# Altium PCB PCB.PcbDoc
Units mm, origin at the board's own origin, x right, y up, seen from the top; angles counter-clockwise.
Board outline 37 x 42.5 mm, 2 copper layers (Top Layer, Bottom Layer); 37 components, 35 nets, 169 pads, 249 vias.
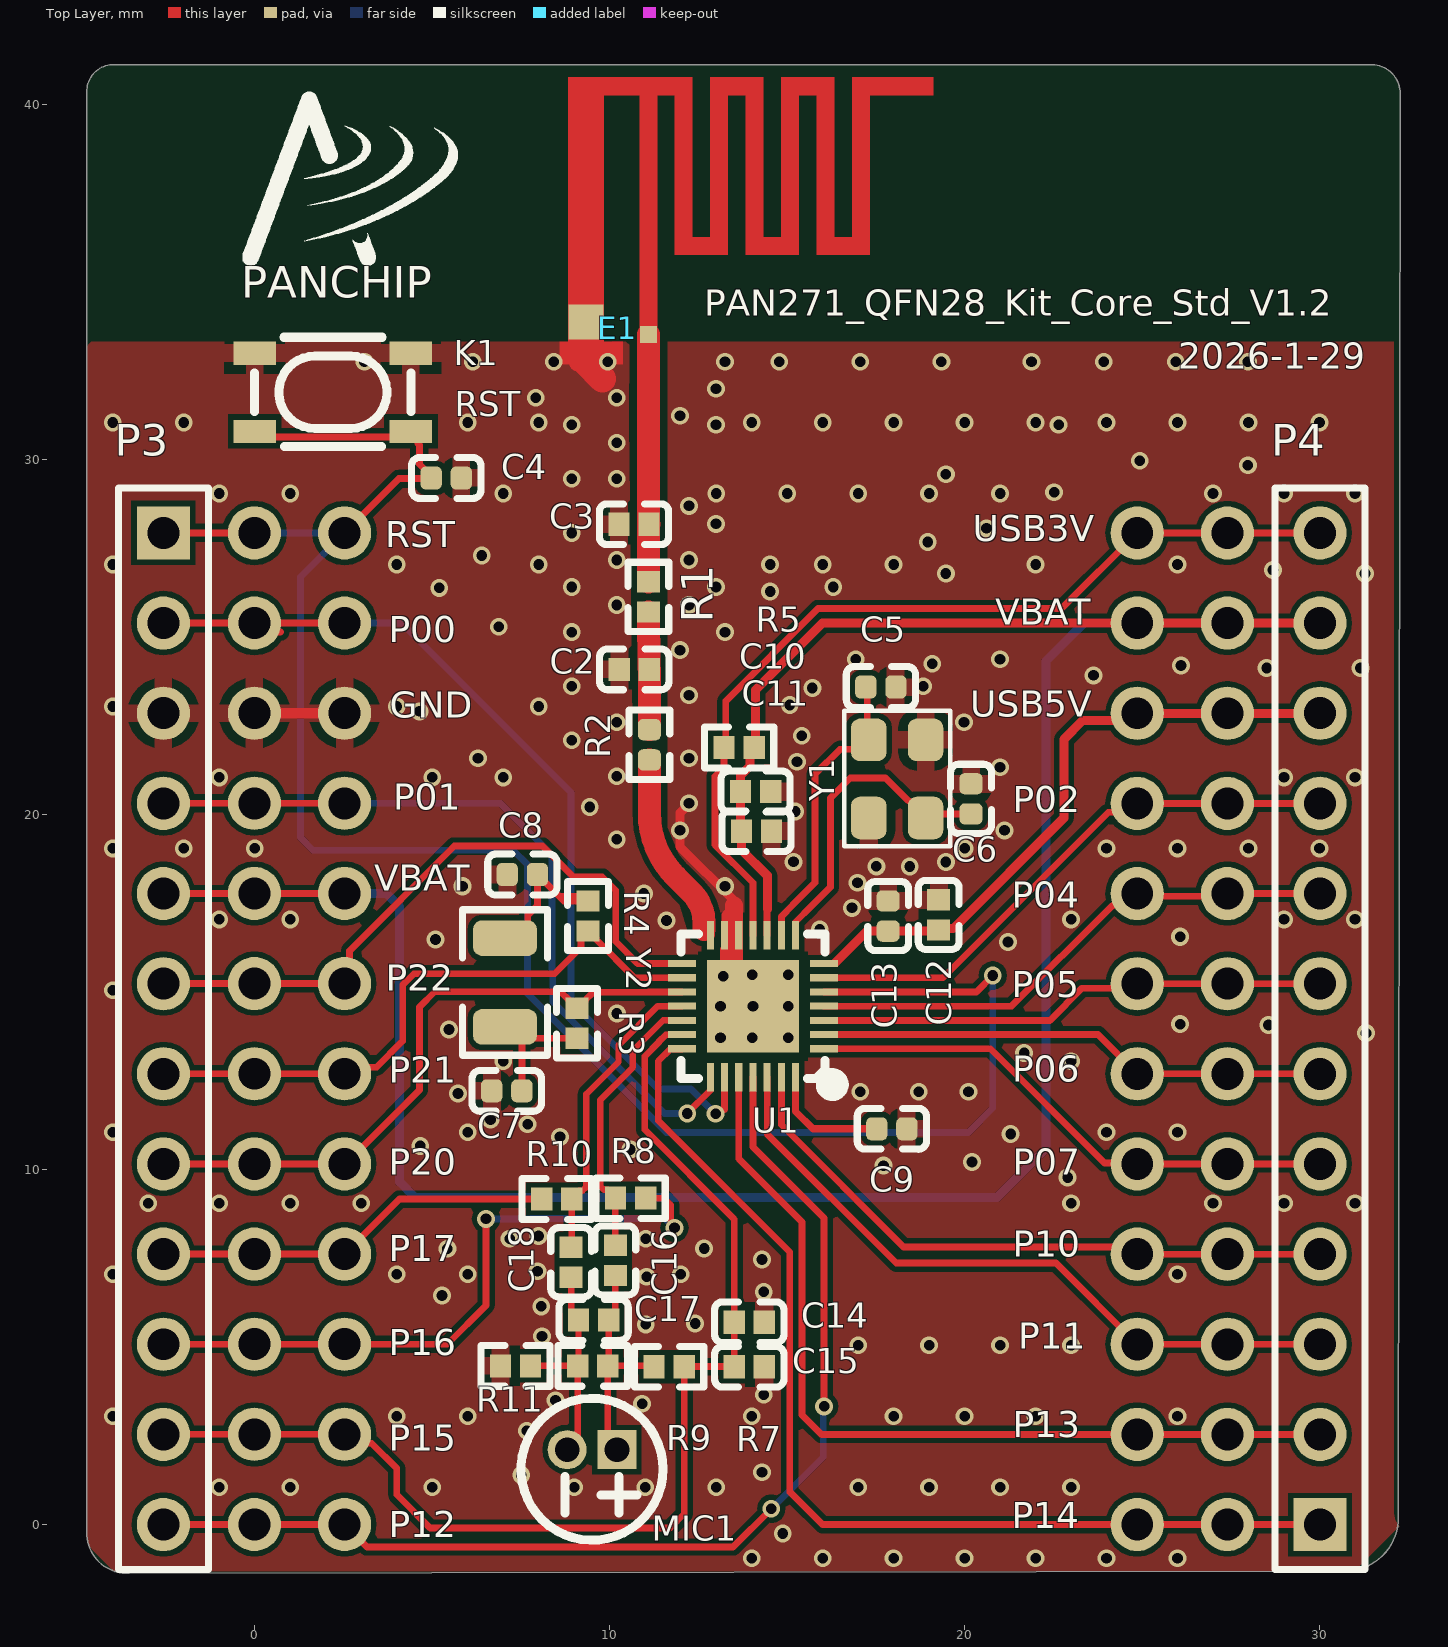
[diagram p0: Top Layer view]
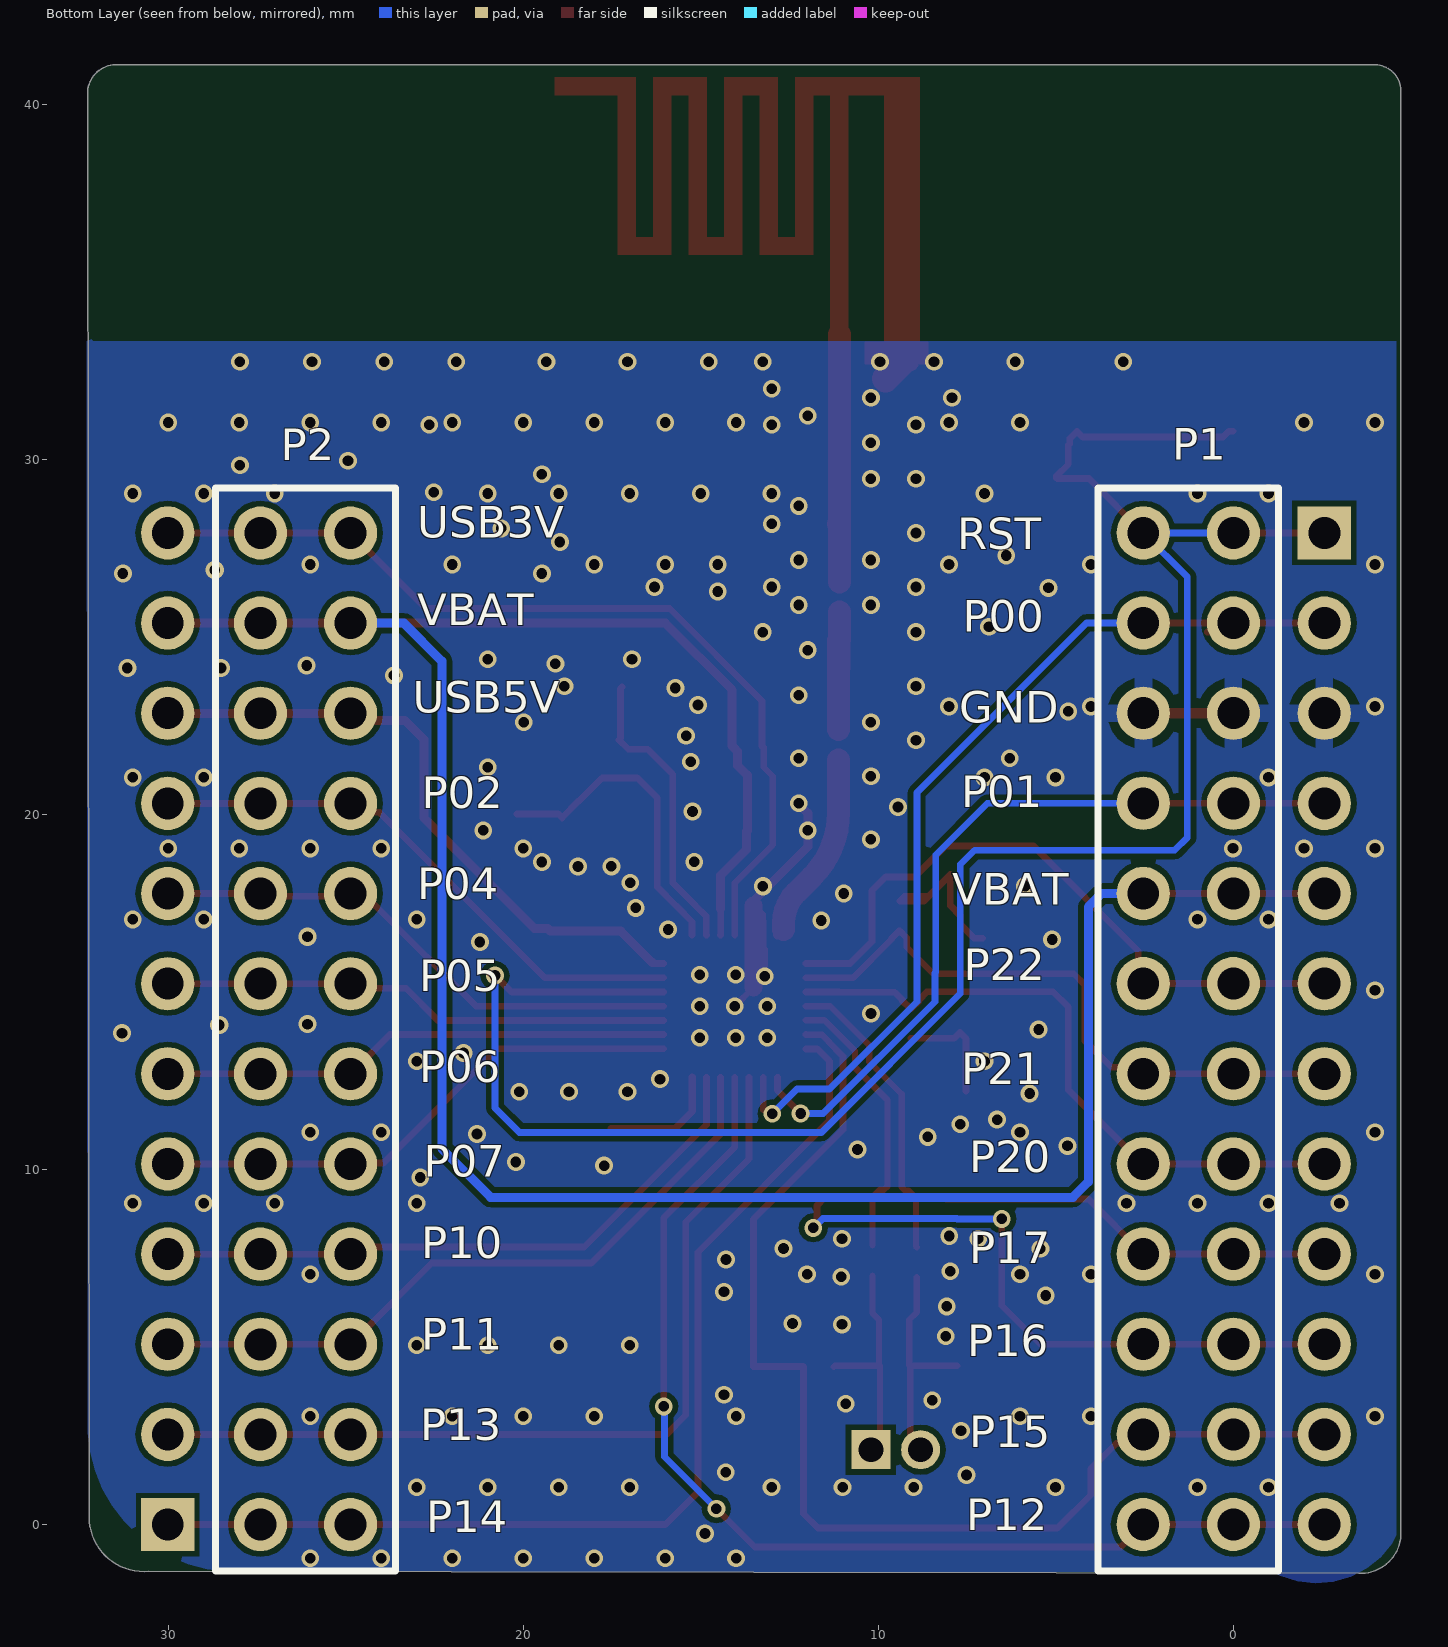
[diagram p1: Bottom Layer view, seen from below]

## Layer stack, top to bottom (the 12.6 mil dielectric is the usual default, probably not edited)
Top Solder: solder mask 0.0102, Solder Resist, Dk 3.5
Top Layer: signal copper 0.0356
Dielectric1: dielectric 0.32, FR-4, Dk 4.8
Bottom Layer: signal copper 0.0356
Bottom Solder: solder mask 0.0102, Solder Resist, Dk 3.5

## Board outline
-4.719,-0.306 -4.719,40.359 cw(c-3.98,40.39) -4.011,41.129 31.499,41.129 cw(c31.482,40.325) 32.285,40.309 32.235,0.075 cw(c30.699,0.215) 30.559,-1.322 30.559,-1.323 -3.528,-1.373 cw(c-3.59,-0.244)

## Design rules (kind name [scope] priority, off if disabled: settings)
Clearance Clearance_SMT [OnLayer('Keep-Out Layer')] p1: gap=0.127
Clearance Clearance_ANT [InNetClass('ANT_Class')] p2: gap=0.117
Clearance [All] p3: gap=0.152
ComponentClearance [All] p1 off: gap=0.254 collisioncheckmode=3 verticalgap=0.254 showdistances=FALSE
DiffPairsRouting [All] p1: maxlimit=0.254 minlimit=0.178 mostfreqgap=0.254 toplayer_minwidth=0.178 toplayer_maxwidth=0.381 toplayer_prefwidth=0.178 bottomlayer_minwidth=0.178 bottomlayer_maxwidth=0.381 bottomlayer_prefwidth=0.178 maxuncoupledlength=12.7
HoleSize [All] p1: absolutevalues=TRUE maxlimit=2.54 minlimit=0.254 maxpercent=80.000 minpercent=20.000
HoleToHoleClearance [All] p1: gap=0.2 allowstackedmicrovias=TRUE
MinimumSolderMaskSliver MinimumSolderMaskSliver_1 [HasFootprint('QFN-28_5x5x05P')] p1: minsoldermaskwidth=0.017
MinimumSolderMaskSliver [All] p2: minsoldermaskwidth=0.02
NetAntennae [All] p1 off: netantennaetolerance=0
PlaneConnect [All] p1: planeconnectstyle=Relief reliefexpansion=0.508 reliefentries=4 reliefconductorwidth=0.508 reliefairgap=0.254
PolygonConnect PolygonConnect_VIA [IsVia] p1: connectstyle=Direct reliefconductorwidth=0.254 reliefentries=4 polygonreliefangle="90 Angle" airgapwidth=0.254
PolygonConnect [All] p2: connectstyle=Relief reliefconductorwidth=0.508 reliefentries=4 polygonreliefangle="90 Angle" airgapwidth=0.254
RoomDefinition ANT [False] p1: confinementstyle=ConfineIn formatcopy=TRUE lockcomponents=FALSE outline 7.061,40.999 25.248,40.999 25.248,32.099 7.061,32.099
RoutingVias [All] p1: holewidth=0.4 width=0.5 viastyle="Through Hole" minholewidth=0.3 minwidth=0.5 maxholewidth=0.5 maxwidth=0.7
ShortCircuit ShortCircuit_ANT [WithinRoom('ANT')] p1: allowed=TRUE
ShortCircuit [All] p2: allowed=FALSE
SilkToSilkClearance [All] p1: silktosilkclearance=0
SilkToSolderMaskClearance SilkToSolderMaskClearance_U10 [HasFootprint('U2')] p1: minsilkscreentomaskgap=0.051 clearancetoexposedcopper=TRUE
SilkToSolderMaskClearance [IsPad] p2: minsilkscreentomaskgap=0 clearancetoexposedcopper=TRUE
SolderMaskExpansion SolderMaskExpansion_1 [IsVia] p1: expansion=0.102
Width [All] p1: maxlimit=1.27 minlimit=0.191 preferedwidth=0.191
20 further rules are at their usual default settings.

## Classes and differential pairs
differential pair mic1: +mic1_p -mic1_n
differential pair mic: +mic_p -mic_n

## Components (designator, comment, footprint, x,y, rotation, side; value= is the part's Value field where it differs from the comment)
C2 "NC" 0402_C#1 10.703,24.094 r180 top
C3 "NC" 0402_C#1 10.696,28.183 r180 top
C4 "100nF / NC" 0402_C#2 5.406,29.488 r180 top
C5 "NC" 0402_C#2 17.653,23.597 r0 top
C6 "NC" 0402_C#2 20.193,20.447 r90 top
C7 "18pF" 0402_C#2 7.112,12.217 r180 top
C8 "18pF" 0402_C#2 7.551,18.313 r180 top
C9 "NC" 0402_C#2 17.96,11.149 r180 top
C10 "4.7uF" 0402_C#1 14.122,20.65 r180 top
C11 "100nF" 0402_C#1 14.148,19.533 r180 top
C12 "100nF" 0402_C#1 19.281,17.176 r270 top
C13 "4.7uF" 0402_C#2 17.859,17.144 r270 top
C14 "NC/4.7uF" 0402_C#1 13.943,5.699 r180 top
C15 "NC/100nF" 0402_C#1 13.945,4.445 r180 top
C16 "NC/1uF" 0402_C#1 10.169,7.441 r270 top
C17 "NC" 0402_C#1 9.56,5.765 r180 top
C18 "NC/1uF" 0402_C#1 8.925,7.39 r270 top
E1 "ANT_PCB" 2.4G_PF_SUB1.5mm_ADD1 9.347,33.579 r90 top
K1 "K2-1808GN-A4SW-04" KEY-SMD_4P-L4.2-W3.2-P2.20-LS5.1-TL 2.21,31.902 r180 top
MIC1 "GMI4015P-2C-60db" MIC-TH_BD4.0-P1.40-D0.4-L-FD 9.513,2.107 r180 top
P1 "Header 2x12" "Header 2X12" 2.54,27.94 r270 bottom locked
P2 "Header 2x12" "Header 2X12" 27.415,27.938 r270 bottom locked
P3 "nc" HDR1X12 -2.563,27.939 r270 top
P4 "nc" HDR1X12 30.025,-0.001 r90 top
R1 "0Ω" 0402_R#1 11.1,26.137 r90 top
R2 "0Ω" 0402_R#2 11.128,21.97 r90 top
R3 "NC" 0402_R#1 9.093,14.122 r270 top
R4 "NC" 0402_R#1 9.398,17.145 r90 top
R5 "NC" 0402_R#1 13.658,21.895 r180 top
R7 "2.2KΩ" 0402_R#1 11.687,4.444 r0 top
R8 "0Ω" 0402_R#1 10.601,9.194 r180 top
R9 "NC" 0402_R#1 9.534,4.469 r0 top
R10 "0Ω" 0402_R#1 8.518,9.168 r0 top
R11 "2.2KΩ" 0402_R#1 7.357,4.469 r0 top
U1 "pn271_qfn28" QFN28_L4.0_W4.0_P0.40_BL_EP 14.049,14.604 r90 top
Y1 "32MHz 10pF ±10ppm" SMD-3225_4P_S 18.11,21.006 r90 top
Y2 "32.768KHz" "SMD-3215_2P FC - 135" 7.061,15.271 r90 top

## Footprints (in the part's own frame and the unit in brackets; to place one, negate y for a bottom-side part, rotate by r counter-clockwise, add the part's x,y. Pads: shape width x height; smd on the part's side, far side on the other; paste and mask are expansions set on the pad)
2.4G_PF_SUB1.5mm_ADD1 [mil] "FR4_PCB with 1.6mm thickness"
  rect 19x19 smd: 1(-2,-69)
  rect 39x39 smd: 2(12,0)
  Top Layer region: 283.31,-19.48 283.31,19.89 -12,19.89 -12,-19.48
  Top Layer region: 283.31,-314.76 263.61,-314.76 263.61,-385 283.31,-385
  Top Layer region: 283.31,-236.02 283.31,-216.33 86.46,-216.33 86.46,-236.02 283.31,-236.02
  Top Layer region: 283.31,-314.76 283.31,-295.07 86.46,-295.07 86.46,-314.76 283.31,-314.76
  Top Layer region: 283.31,-196.64 283.31,-176.96 86.46,-176.96 86.46,-196.64 283.31,-196.64
  Top Layer region: 283.31,-275.39 283.31,-255.7 86.46,-255.7 86.46,-275.39 283.31,-275.39
  Top Layer region: 283.31,-157.28 283.31,-137.59 86.46,-137.59 86.46,-157.28 283.31,-157.28
  Top Layer region: 283.31,-255.7 283.31,-236.02 263.62,-236.02 263.62,-255.7 283.31,-255.7
  Top Layer region: 283.31,-117.91 283.31,-19.48 263.62,-19.48 263.62,-98.22 86.46,-98.22 86.46,-117.91 283.31,-117.91
  Top Layer region: 283.31,-176.96 283.31,-157.28 263.62,-157.28 263.62,-176.96 283.31,-176.96
  Top Layer region: 106.14,-137.59 106.14,-117.91 86.46,-117.91 86.46,-137.59 106.14,-137.59
  Top Layer region: 106.14,-275.39 86.46,-275.39 86.46,-295.07 106.14,-295.07 106.14,-275.39
  Top Layer region: 106.14,-216.33 106.14,-196.65 86.46,-196.65 86.46,-216.33 106.14,-216.33
  Top Layer region: 263.79,-79.16 263.79,-59.48 -12,-59.48 -12,-79.16
0402_C#1 [mm]
  rect 0.6x0.65 smd mask+0.051: 1(-0.425,0) 2(0.425,0)
  silkscreen extent -0.97,-0.58 0.97,0.58, body extent -0.48,-0.3 0.52,0.3, height 0.2
0402_C#2 [mm]
  rrect50% 0.6x0.65 smd mask+0.051: 1(-0.425,0) 2(0.425,0)
  silkscreen extent -0.97,-0.58 0.98,0.58, body extent -0.48,-0.3 0.52,0.3, height 0.2
0402_R#1 [mm]
  rect 0.6x0.65 smd mask+0.051: 1(-0.425,0) 2(0.425,0)
  silkscreen extent -0.97,-0.58 0.97,0.58, body extent -0.57,-0.27 0.58,0.28, height 0.41
0402_R#2 [mm]
  rrect50% 0.6x0.65 smd mask+0.051: 1(-0.425,0) 2(0.425,0)
  silkscreen extent -0.97,-0.58 0.97,0.58, body extent -0.57,-0.27 0.58,0.28, height 0.41
HDR1X12 [mm] "Connector; Header; 12 Position"
  rect 1.5x1.5 hole 0.9: 1(0,0)
  round 1.5 hole 0.9: 2(2.54,0) 3(5.08,0) 4(7.62,0) 5(10.16,0) 6(12.7,0) 7(15.24,0) 8(17.78,0) 9(20.32,0) 10(22.86,0) 11(25.4,0) 12(27.94,0)
  silkscreen extent -1.27,-1.27 29.21,1.27
"Header 2X12" [mm] "Connector; Header; 12x2 Position"
  round 1.5 hole 0.9: 1(0,0) 2(0,2.54) 3(2.54,0) 4(2.54,2.54) 5(5.08,0) 6(5.08,2.54) 7(7.62,0) 8(7.62,2.54) 9(10.16,0) 10(10.16,2.54) 11(12.7,0) 12(12.7,2.54) 13(15.24,0) 14(15.24,2.54) 15(17.78,0) 16(17.78,2.54) 17(20.32,0) 18(20.32,2.54) 19(22.86,0) 20(22.86,2.54) 21(25.4,0) 22(25.4,2.54) 23(27.94,0) 24(27.94,2.54)
  silkscreen extent -1.27,-1.27 29.25,3.81, body extent -1.27,-1.27 29.21,3.81, height 8.5
KEY-SMD_4P-L4.2-W3.2-P2.20-LS5.1-TL [mm]
  rect 1.2x0.65 smd: 1(-2.2,1.1) 2(2.2,1.1) 3(-2.2,-1.1) 4(2.2,-1.1)
  silkscreen extent -2.2,-1.55 2.2,1.52, body extent -2.55,-1.6 2.65,1.65, height 2.5
MIC-TH_BD4.0-P1.40-D0.4-L-FD [mm]
  rect 1.1x1.1 hole 0.7: 1(-0.7,0)
  round 1.1 hole 0.7: 2(0.7,0)
  silkscreen extent -2,-1.45 2,2.55
QFN28_L4.0_W4.0_P0.40_BL_EP [mm] "271_qfn28_sram"
  rect 0.2x0.8 smd: 1(-1.2,-2) 2(-0.8,-2) 3(-0.4,-2) 4(0,-2) 5(0.4,-2) 6(0.8,-2) 7(1.2,-2) 15(1.2,2) 16(0.8,2) 17(0.4,2) 18(0,2) 19(-0.4,2) 20(-0.8,2) 21(-1.2,2)
  rect 0.8x0.2 smd: 8(2,-1.2) 9(2,-0.8) 10(2,-0.4) 11(2,0) 12(2,0.4) 13(2,0.8) 14(2,1.2) 22(-2,1.2) 23(-2,0.8) 24(-2,0.4) 25(-2,0) 26(-2,-0.4) 27(-2,-0.8) 28(-2,-1.2)
  rect 2.6x2.6 smd: 29(0,0)
  silkscreen extent -2.03,-2.03 2.03,2.03, body extent -1.94,-2.04 2.06,1.96, height 0.75
"SMD-3215_2P FC - 135" [mm]
  rrect50% 1x1.8 smd: 1(-1.25,0) 2(1.25,0)
  silkscreen extent -2.05,-1.2 2.05,1.2, body extent -1.6,-0.75 1.6,0.75, height 0.9
SMD-3225_4P_S [mm]
  rrect50% 1.2x1 smd: 1(1.1,0.8) 2(-1.1,0.8) 3(-1.1,-0.8) 4(1.1,-0.8)
  silkscreen extent -1.9,-1.5 1.92,1.5, body extent -1.6,-1.25 1.6,1.25, height 0.7

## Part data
C2 C3: library part "0402 1nF (102) 10% 50V", "贴片电容"
C4 C9 C13: library part "0402 100nF (104) 10% 16V", "贴片电容"
C5 C6 C7 C8: library part "0402 20pF (200) 5% 50V", "贴片电容"
C10 C11 C12 C14 C15 C16 C17 C18: library part "0402 4.7uF (475) 20% 10V", "贴片电容"
E1: "NC"
P1 P2: "Header 2x11,2.54mm"
P3 P4: library part "Header 12", "Header, 12-Pin"
R1 R2 R3 R4 R5 R9 R11: library part "0402 0Ω (0R0) 1%", "贴片电阻"
R7: library part "0402 2.2KΩ (2201) 1%", "贴片电阻"
R8 R10: library part "0402 0Ω (0R0) 1%"
Y1: library part "Crystal 4pin", "C113671"
Y2: library part "DT26N 32.768KHz", "C620155, X321532768KGD2SI,12.5pF"

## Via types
v1: diameter 0.5, hole 0.3, Top Layer to Bottom Layer, tented both sides, 222 vias
v2: diameter 0.508, hole 0.305, Top Layer to Bottom Layer, tented both sides, 27 vias

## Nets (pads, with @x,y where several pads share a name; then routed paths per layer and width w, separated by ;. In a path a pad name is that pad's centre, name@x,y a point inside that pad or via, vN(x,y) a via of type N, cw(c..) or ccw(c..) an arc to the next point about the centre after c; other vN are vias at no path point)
ANT: R2.1 U1.14 | length 5.9
  Top Layer w0.254: 12.714,17.251 cw(c12.389,16.926) 12.849,16.926 U1.14
  Top Layer w0.65: R2.1 11.128,20.05 ccw(c13.668,20.05) 11.872,18.254 12.322,17.804 cw(c11.477,16.96) 12.671,16.96 12.671,16.765
GND: C2.2 C3.2 C4.1 C5.2 C6.2 C7.2 C8.2 C9.1 C10.1 C11.1 C12.1 C13.1 C14.1 C15.1 E1.2 K1.3 K1.4 P1.5 P1.6 P3.3 R11.1 U1.12 U1.13 U1.29 Y1.2 Y1.4 | length 14.8
  Top Layer w0.191: 13.515,17.441 13.262,17.188 13.262,17.024 13.253,17.016 13.253,16.609 U1.13 13.244,16.599 13.244,16.234 13.208,16.198 13.208,16.078 v1(13.208,15.444) 13.515,15.137 v1(14.049,14.604)
  Top Layer w0.254: v1(12.245,20.319) 12.245,20.301 11.991,20.047 v1(11.991,19.557) 11.991,19.098 13.515,17.574 13.515,17.441
  Top Layer w0.3: P1.6 P1.5
  Top Layer w0.508: 9.119,32.741 9.302,32.924 9.302,33.838 E1.2 ; U1.29@13.515,15.137 13.515,17.441
  Top Layer w0.762: E1.2 9.347,32.741 9.804,32.283
  other v1: 14.011,-0.95 16.011,-0.95 18.011,-0.95 20.011,-0.95 22.011,-0.95 24.011,-0.95 26.011,-0.95 14.887,-0.255 -0.989,1.05 1.011,1.05 5.011,1.05 9.011,1.05 11.011,1.05 13.011,1.05 17.011,1.05 19.011,1.05 21.011,1.05 23.011,1.05 7.521,1.396 14.303,1.472 7.673,2.64 -3.989,3.05 4.011,3.05 6.011,3.05 14.011,3.05 18.011,3.05 20.011,3.05 22.011,3.05 26.011,3.05 10.925,3.402 8.486,3.504 14.351,3.658 17.011,5.05 19.011,5.05 21.011,5.05 23.011,5.05 8.105,5.307 11.026,5.638 8.08,6.146 5.286,6.45 14.351,6.553 11.052,6.984 -3.989,7.05 4.011,7.05 6.011,7.05 12.011,7.05 26.011,7.05 7.978,7.136 5.438,7.771 7.191,8.051 11.026,8.051 8.004,8.127 -2.989,9.05 -0.989,9.05 1.011,9.05 3.011,9.05 23.011,9.05 27.011,9.05 29.011,9.05 31.011,9.05 22.913,9.778 4.676,10.667 8.613,10.921 -3.989,11.05 6.011,11.05 24.011,11.05 26.011,11.05 7.699,11.276 17.071,12.191 18.722,12.191 20.119,12.191 7.011,13.05 23.011,13.05 13.134,13.715 14.023,13.715 15.039,13.715 13.134,14.604 15.039,14.604 -3.989,15.05 14.023,15.493 15.039,15.493 15.928,16.763 11.61,17.017 -0.989,17.05 1.011,17.05 23.011,17.05 29.011,17.05 31.011,17.05 16.84,17.374 10.975,17.779 16.993,18.085 17.526,18.542 18.468,18.541 15.189,18.669 19.484,18.668 -3.989,19.05 -1.989,19.05 0.011,19.05 20.011,19.05 24.011,19.05 26.011,19.05 28.011,19.05 30.011,19.05 10.213,19.303 21.135,19.557 15.24,20.091 9.451,20.217 -0.989,21.05 5.011,21.05 7.011,21.05 29.011,21.05 31.011,21.05 10.213,21.081 21.008,21.335 15.291,21.488 6.302,21.589 12.245,21.589 8.943,22.097 15.42,22.224 10.213,22.605 19.992,22.605 4.651,22.91 -3.989,23.05 4.011,23.05 8.011,23.05 15.088,23.089 12.245,23.367 15.723,23.571 8.943,23.621 18.849,23.621 19.103,24.256 16.944,24.383 21.008,24.383 11.991,24.637 8.943,25.145 13.261,25.145 6.886,25.297 10.213,25.907 12.245,25.907 14.531,26.288 5.21,26.389 8.943,26.415 13.007,26.415 16.309,26.415 19.484,26.796 -3.989,27.05 4.011,27.05 8.011,27.05 14.531,27.05 16.011,27.05 18.011,27.05 22.011,27.05 26.011,27.05 10.213,27.177 12.245,27.177 6.403,27.304 18.976,27.685 8.943,27.939 20.627,28.066 13.007,28.193 12.245,28.701 -0.989,29.05 1.011,29.05 7.011,29.05 13.011,29.05 15.011,29.05 17.011,29.05 19.011,29.05 21.011,29.05 27.011,29.05 29.011,29.05 31.011,29.05 22.532,29.082 8.943,29.463 10.213,29.463 19.484,29.59 27.993,29.844 24.945,29.971 10.213,30.479 8.943,30.987 13.007,30.987 22.659,30.987 -3.989,31.05 -1.989,31.05 6.011,31.05 8.011,31.05 14.011,31.05 16.011,31.05 18.011,31.05 20.011,31.05 22.011,31.05 24.011,31.05 26.011,31.05 28.011,31.05 30.011,31.05 11.991,31.241 7.927,31.749 10.213,31.749 13.007,32.003 3.101,32.765 6.149,32.765 8.435,32.765 9.959,32.765 13.261,32.765 14.785,32.765 17.071,32.765 19.357,32.765 21.897,32.765 23.929,32.765 25.961,32.765 27.993,32.765
  other v2: 12.421,5.664 14.3,7.468 12.675,7.772 17.729,10.109 20.218,10.211 10.592,10.566 21.311,10.998 6.655,11.405 5.74,12.141 16.154,12.548 21.692,13.284 31.318,13.843 5.486,13.945 28.575,14.072 26.086,14.097 10.211,14.402 21.234,16.408 5.105,16.485 26.086,16.561 5.867,17.983 13.259,17.983 23.647,23.927 28.524,24.13 31.166,24.13 26.111,24.206 31.293,26.797 28.702,26.899
mic1_n: C18.1 R10.2 U1.18 | length 8.5
  Top Layer w0.178: C18.1 8.943,7.834 8.943,9.193 9.155,9.404 9.243,9.404 9.347,9.508 9.347,12.128 10.262,13.042 10.262,13.508 11.357,14.604 U1.18
mic1_p: C16.1 R8.2 U1.19 | length 7.8
  Top Layer w0.178: C16.1 10.169,9.187 R8.2 10.176,9.219 9.965,9.43 9.851,9.43 9.747,9.534 9.747,11.962 10.662,12.877 10.662,13.343 11.523,14.204 U1.19
mic_n: C17.2 C18.2 MIC1.2 R9.1 R11.2 | length 6.4
  Top Layer w0.178: R11.2 R9.1 ; MIC1.2 8.813,2.139 9.109,2.435 R9.1 ; C18.2 8.925,5.975 C17.2 9.135,4.495 R9.1
mic_p: C16.2 C17.1 MIC1.1 R7.1 R9.2 | length 6.4
  Top Layer w0.178: C16.2 10.169,5.949 C17.1 9.985,4.495 R9.2 ; MIC1.1 10.159,2.161 10.159,2.226 9.959,2.426 R9.2 ; R7.1 11.236,4.469 R9.2
NetC2_1: C2.1 R1.1 R2.2 | length 3.3
  Top Layer w0.6: C2.1@11.119,24.128 11.128,24.119 C2.1
  Top Layer w0.65: R1.1 11.1,24.929 11.119,24.91 C2.1@11.119,24.128 ; R2.2 11.128,22.781 C2.1
NetC3_1: C3.1 E1.1 R1.2 | length 7
  Top Layer w0.65: R1.2 11.1,28.162 C3.1 11.1,28.204 E1.1
NetC7_1: C7.1 R3.2 Y2.1 | length 3.2
  Top Layer w0.191: C7.1 7.537,13.689 7.707,13.859 7.868,13.697 R3.2
NetC8_1: C8.1 R4.2 Y2.2 | length 4.9
  Top Layer w0.191: Y2.2 7.307,16.521 7.7,16.914 7.7,17.159 7.976,17.435 7.976,17.697 C8.1 8.592,17.697 ; 8.592,17.697 9.271,17.697 R4.2 8.719,17.57 8.592,17.697
NetC9_2: C9.2 U1.28 | length 3.5
  Top Layer w0.2: U1.28 15.249,11.638 15.738,11.149 C9.2
P00: P1.3 P1.4 P3.2 U1.23 | length 26.5
  Top Layer w0.191: P3.2 P1.4 P1.4 ; 0.736,25.149 0.251,25.149 0.125,25.275 0.251,25.4 P1.3 ; v1(12.995,11.571) 13.078,11.571 13.203,11.696 13.247,11.696 13.249,11.698 U1.23
  Bottom Layer w0.191: P1.3 4.142,25.4 8.918,20.624 8.918,14.729 11.379,12.268 12.297,12.268 v1(12.995,11.571)
P01: P1.7 P1.8 P3.4 U1.22 | length 22.1
  Top Layer w0.191: P3.4 -2.562,20.32 P1.8 P1.7 ; v1@12.167,11.553 v1(12.195,11.581) 12.844,12.23 12.844,12.599 U1.22
  Bottom Layer w0.191: P1.7 6.936,20.32 8.385,18.871 8.385,15.567 8.41,15.541 8.41,14.729 11.558,11.581 v1(12.195,11.581)
P02: P2.7 P2.8 P4.9 U1.6 | length 16
  Top Layer w0.191: U1.6 19.396,15.404 24.059,20.067 24.625,20.067 P2.8 P2.7 30.024,20.318 P4.9
P03: C4.2 K1.1 K1.2 P1.1 P1.2 P3.1 U1.5 | length 57.4
  Top Layer w0.191: P3.1 -2.562,27.94 P1.2 ; K1.2 0.132,30.802 0.294,30.641 4.248,30.641 K1.1 4.61,30.602 4.61,30.459 4.651,30.418 4.651,29.873 4.981,29.543 C4.2 4.963,29.47 4.07,29.47 P1.1 ; U1.5 20.342,15.004 v1(20.805,15.467)
  Bottom Layer w0.191: P1.2 P1.1 1.298,26.698 1.298,19.354 1.654,18.998 7.291,18.998 7.696,18.593 7.696,14.958 11.607,11.048 20.119,11.048 20.805,11.734 v1(20.805,15.467)
P04: P2.9 P2.10 P4.8 U1.4 | length 15.4
  Top Layer w0.191: U1.4 21.339,14.604 24.152,17.417 24.161,17.417 24.521,17.778 P2.10 24.95,17.703 27.34,17.703 P2.9 27.417,17.779 P4.8
P05: P2.11 P2.12 P4.7 U1.3 | length 14.4
  Top Layer w0.191: U1.3 22.412,14.204 23.32,15.112 24.75,15.112 P2.12 P2.11 30.024,15.238 P4.7
P06: P2.13 P2.14 P4.6 U1.2 | length 14.4
  Top Layer w0.191: U1.2 23.769,13.804 P2.14 P2.13 30.024,12.698 P4.6
P07: P2.15 P2.16 P4.5 U1.1 | length 14.5
  Top Layer w0.191: U1.1 20.735,13.404 23.951,10.188 24.845,10.188 P2.16 24.877,10.159 26.622,10.159 ; P2.15 30.024,10.158 P4.5
P10: P2.17 P2.18 P4.4 U1.27 | length 18
  Top Layer w0.191: U1.27 14.849,11.264 18.291,7.822 24.671,7.822 P2.18 P2.17 30.024,7.618 P4.4
P11: P2.19 P2.20 P4.3 U1.26 | length 19.6
  Top Layer w0.191: U1.26 14.449,11.003 18.086,7.366 22.587,7.366 P2.20 P2.19 30.024,5.078 P4.3
P12: P1.23 P1.24 P3.12 U1.25 | length 31.4
  Top Layer w0.191: P3.12 -2.562,0 P1.24 P1.23 3.175,-0.635 13.487,-0.635 v1(14.567,0.445) ; U1.25 14.049,10.64 16.053,8.636 v1(16.053,3.327)
  Bottom Layer w0.191: v1(14.567,0.445) 16.032,1.909 v1@16.032,3.327
P13: P2.21 P2.22 P4.2 U1.24 | length 25.1
  Top Layer w0.191: U1.24 13.649,10.303 15.43,8.522 15.43,3.086 15.979,2.538 P2.22 P2.21 30.024,2.538 P4.2
P14: P2.23 P2.24 P4.1 U1.21 | length 29.8
  Top Layer w0.191: U1.21 12.044,13.399 11.723,13.399 11.379,13.056 11.379,11.379 15.088,7.671 15.088,0.914 16.004,-0.002 P2.24 P2.23 30.024,-0.002 P4.1
P15: C14.2 C15.2 P1.21 P1.22 P3.11 R7.2 U1.20 | length 33
  Top Layer w0.191: P3.11 -2.562,2.54 P1.22 P1.21 2.791,2.289 3.299,2.289 4.013,1.575 4.013,0.838 4.953,-0.102 11.708,-0.102 12.112,0.302 R7.2 12.118,4.451 C15.2@13.52,4.451 ; U1.20 12.044,13.799 11.594,13.799 11.401,13.606 11.401,13.594 10.998,13.191 10.998,11.125 13.52,8.604 C15.2@13.52,4.451 ; C15.2 C15.2@13.52,4.451
P16_DIP: P1.19 P1.20 P3.10 R8.1 | length 18.9
  Top Layer w0.191: P3.10 5.434,5.079 6.528,6.172 v1(6.528,8.611) ; R8.1 11.533,9.194 11.735,8.992 11.735,8.382 11.811,8.382 v1(11.836,8.357)
  Bottom Layer w0.191: v1(6.528,8.611) 7.784,8.611 7.797,8.624 11.569,8.624 v1(11.836,8.357) v1@11.836,8.382
P17_DIP: P1.17 P1.18 P3.9 R10.1 | length 11.3
  Top Layer w0.191: P3.9 -2.562,7.62 P1.18 P1.17 4.088,9.168 R10.1
P20: P1.15 P1.16 P3.8 R3.1 U1.17 | length 18.6
  Top Layer w0.191: P3.8 -2.562,10.16 P1.16 P1.15 2.847,10.16 2.847,10.438 4.651,12.242 4.651,14.578 5.083,15.01 8.63,15.01 8.863,14.777 8.863,14.752 9.068,14.547 R3.1 9.118,14.547 9.323,14.752 9.323,14.777 9.54,14.994 11.093,14.994 11.102,15.004 U1.17
P21: P1.13 P1.14 P3.7 R4.1 U1.16 | length 17.9
  Top Layer w0.191: P3.7 -2.562,12.7 P1.14 P1.13 2.724,12.884 3.439,12.884 4.179,13.624 4.179,15.199 4.498,15.518 8.457,15.518 9.204,16.266 9.204,16.526 R4.1 9.423,16.72 9.628,16.515 9.628,16.49 10.714,15.404 U1.16
P22: P1.11 P1.12 P3.6 U1.15 | length 18.9
  Top Layer w0.191: P3.6 -2.562,15.24 P1.12 P1.11 2.681,15.381 2.681,16.164 5.631,19.115 8.116,19.115 8.986,18.245 9.8,18.245 10.181,17.863 10.181,16.422 10.799,15.804 U1.15
VBAT: C10.2 C11.2 P1.9 P1.10 P2.3 P2.4 P3.5 P4.11 R5.1 U1.10 | length 74.4
  Top Layer w0.191: P3.5 -2.562,17.78 P1.10 P1.9 ; 14.444,17.337 14.444,16.974 14.444,16.609 U1.10
  Top Layer w0.254: 14.458,17.337 14.458,18.283 13.723,19.018 C11.2 13.697,19.558 C10.2 13.697,21.114 13.968,21.385 13.968,21.779 R5.1 14.125,21.936 14.125,23.519 16.003,25.398 P2.4 P2.3 30.024,25.398 P4.11
  Bottom Layer w0.254: P1.9 3.71,17.78 4.089,17.4 4.089,9.652 4.521,9.22 20.93,9.22 22.301,10.592 22.301,24.329 23.369,25.398 P2.4
VBUS_3V: P2.1 P2.2 P4.12 R5.2 U1.11 | length 25.9
  Top Layer w0.191: R5.2 R5.2@13.233,21.87 ; U1.11 14.049,18.082 12.979,19.152 12.979,21.082 13.233,21.336 R5.2@13.233,21.87 ; P4.12 30.024,27.938 P2.1 P2.2 22.744,25.806 15.882,25.806 13.284,23.208 13.284,21.921 R5.2@13.233,21.87
VBUS_5V: C12.2 C13.2 P2.5 P2.6 P4.10 U1.7 | length 18.2
  Top Layer w0.191: U1.7 U1.7@16.368,15.804 ; C12.2@19.249,16.719 C12.2
  Top Layer w0.254: U1.7@16.368,15.831 17.256,16.719 C13.2 C12.2@19.249,16.719 ; C12.2 19.318,16.788 19.688,16.788 22.812,19.912 22.812,22.122 23.345,22.656 24.673,22.656 P2.6 P2.5 30.024,22.858 P4.10
XC0: C5.1 U1.9 Y1.1 | length 8.4
  Top Layer w0.191: U1.9 14.85,16.605 14.85,17.132 15.167,17.449 15.167,17.453 15.799,18.085 15.799,21.141 16.5,21.842 17.021,21.842 17.047,21.843 Y1.1 17.269,22.147 17.269,23.556 C5.1
XC1: C6.1 U1.8 Y1.3 | length 9
  Top Layer w0.191: U1.8 15.253,16.609 15.253,16.983 15.696,17.426 15.699,17.426 16.231,17.958 16.231,20.472 16.789,21.031 17.785,21.031 18.422,20.394 18.438,20.394 18.91,19.922 Y1.3@18.91,19.91 ; Y1.3 Y1.3@18.91,19.91 ; C6.1 19.022,20.022 Y1.3@18.91,19.91

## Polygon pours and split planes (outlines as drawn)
GND on Bottom Layer "GND_L02_P001" (solid, remove dead copper, pour order 1): -4.595,-0.306 -4.595,35.183 cw(c-1.102,35.183) -1.102,38.675 28.095,38.675 cw(c28.109,34.476) 32.308,34.463 32.285,2.863 cw(c28.109,2.852) 28.098,-1.325 -1.102,-1.325 cw(c-2.339,0.931)
GND on Top Layer "GND_L01_P003" (solid, remove dead copper, pour order 3): -4.696,35.66 ccw(c-4.635,35.599) -4.722,35.599 -4.722,-0.306 ccw(c-4.109,-0.306) -4.542,-0.74 -3.934,-1.347 cw(c-3.873,-1.409) -3.873,-1.322 31.016,-1.322 cw(c31.077,-1.322) 31.034,-1.279 32.261,-0.052 cw(c32.629,0.316) 32.108,0.316 32.108,35.737

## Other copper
Top Layer:
  rectangle net GND: 8.598,32.69 10.389,33.327
  pour cut-out: 10.558,33.327 11.648,33.327 11.648,19.648 11.955,18.906 13.029,17.603 13.249,16.604 12.982,16.382 12.485,16.315 12.185,16.765 11.977,17.46 10.971,18.676 10.671,20.268 10.544,31.063
  pour cut-out: -4.719,41.129 -4.719,33.327 32.235,33.327 32.235,41.129
Bottom Layer:
  pour cut-out: -4.719,33.343 8.534,33.343 32.123,33.343 32.235,33.454 32.235,41.129 -4.719,41.129

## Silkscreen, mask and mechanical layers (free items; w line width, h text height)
Top Overlay:
  drawing of 1098 lines, arcs and shapes, not listed
  text "PANCHIP" at -0.376,34.276 h1.52
  text "PAN271_QFN28_Kit_Core_Std_V1.2" at 12.675,33.807 h1.27
  text "2026-1-29" at 26.035,32.309 h1.27
  text "RST" at 5.641,30.987 h1.2
  text "USB3V" at 20.244,27.457 h1.27
  text "RST" at 3.69,27.286 h1.27
  text "VBAT" at 20.87,25.094 h1.27
  text "P00" at 3.787,24.611 h1.27
  text "USB5V" at 20.168,22.504 h1.27
  text "GND" at 3.81,22.479 h1.27
  text "P01" at 3.912,19.888 h1.27
  text "P02" at 21.373,19.811 h1.27
  text "VBAT" at 3.378,17.602 h1.27
  text "P04" at 21.335,17.118 h1.27
  text "P22" at 3.708,14.783 h1.27
  text "P05" at 21.345,14.604 h1.27
  text "P06" at 21.352,12.216 h1.27
  text "P21" at 3.787,12.192 h1.27
  text "P20" at 3.787,9.6 h1.27
  text "P07" at 21.365,9.6 h1.27
  text "P10" at 21.372,7.289 h1.27
  text "P17" at 3.787,7.162 h1.27
  text "P11" at 21.527,4.698 h1.27
  text "P16" at 3.787,4.52 h1.27
  text "P13" at 21.364,2.209 h1.27
  text "P15" at 3.787,1.828 h1.27
  text "P14" at 21.335,-0.357 h1.27
  text "P12" at 3.787,-0.611 h1.27
Bottom Overlay:
  text "USB3V" at 22.99,27.507 h1.52
  text "RST" at 7.775,27.177 h1.52
  text "VBAT" at 22.99,25.043 h1.52
  text "P00" at 7.623,24.865 h1.52
  text "USB5V" at 23.117,22.579 h1.52
  text "GND" at 7.724,22.3 h1.52
  text "P01" at 7.673,19.912 h1.52
  text "P02" at 22.863,19.887 h1.52
  text "P04" at 22.99,17.322 h1.52
  text "VBAT" at 7.927,17.169 h1.52
  text "P22" at 7.597,15.036 h1.52
  text "P05" at 22.939,14.731 h1.52
  text "P06" at 22.939,12.165 h1.52
  text "P21" at 7.673,12.115 h1.52
  text "P20" at 7.445,9.625 h1.52
  text "P07" at 22.812,9.498 h1.52
  text "P10" at 22.888,7.212 h1.52
  text "P17" at 7.445,7.06 h1.52
  text "P11" at 22.888,4.622 h1.52
  text "P16" at 7.496,4.444 h1.52
  text "P13" at 22.913,2.082 h1.52
  text "P15" at 7.445,1.878 h1.52
  text "P12" at 7.521,-0.458 h1.52
  text "P14" at 22.736,-0.509 h1.52
Mechanical 1:
  lines w0.1: -4.719,-0.306 ccw(c-3.59,-0.244) -3.528,-1.373 30.559,-1.323 ccw(c30.699,0.215) 32.235,0.075 32.285,40.309 ccw(c31.482,40.325) 31.499,41.129 -4.011,41.129 ccw(c-3.98,40.39) -4.719,40.359 -4.719,-0.306
Top Assembly:
  text "板厚 1.6mm" at -2.845,44.272 h1.5

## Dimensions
-4.719,40.359 to 32.235,0.075 on Top Overlay
-4.011,41.129 to -3.528,-1.373 on Top Overlay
